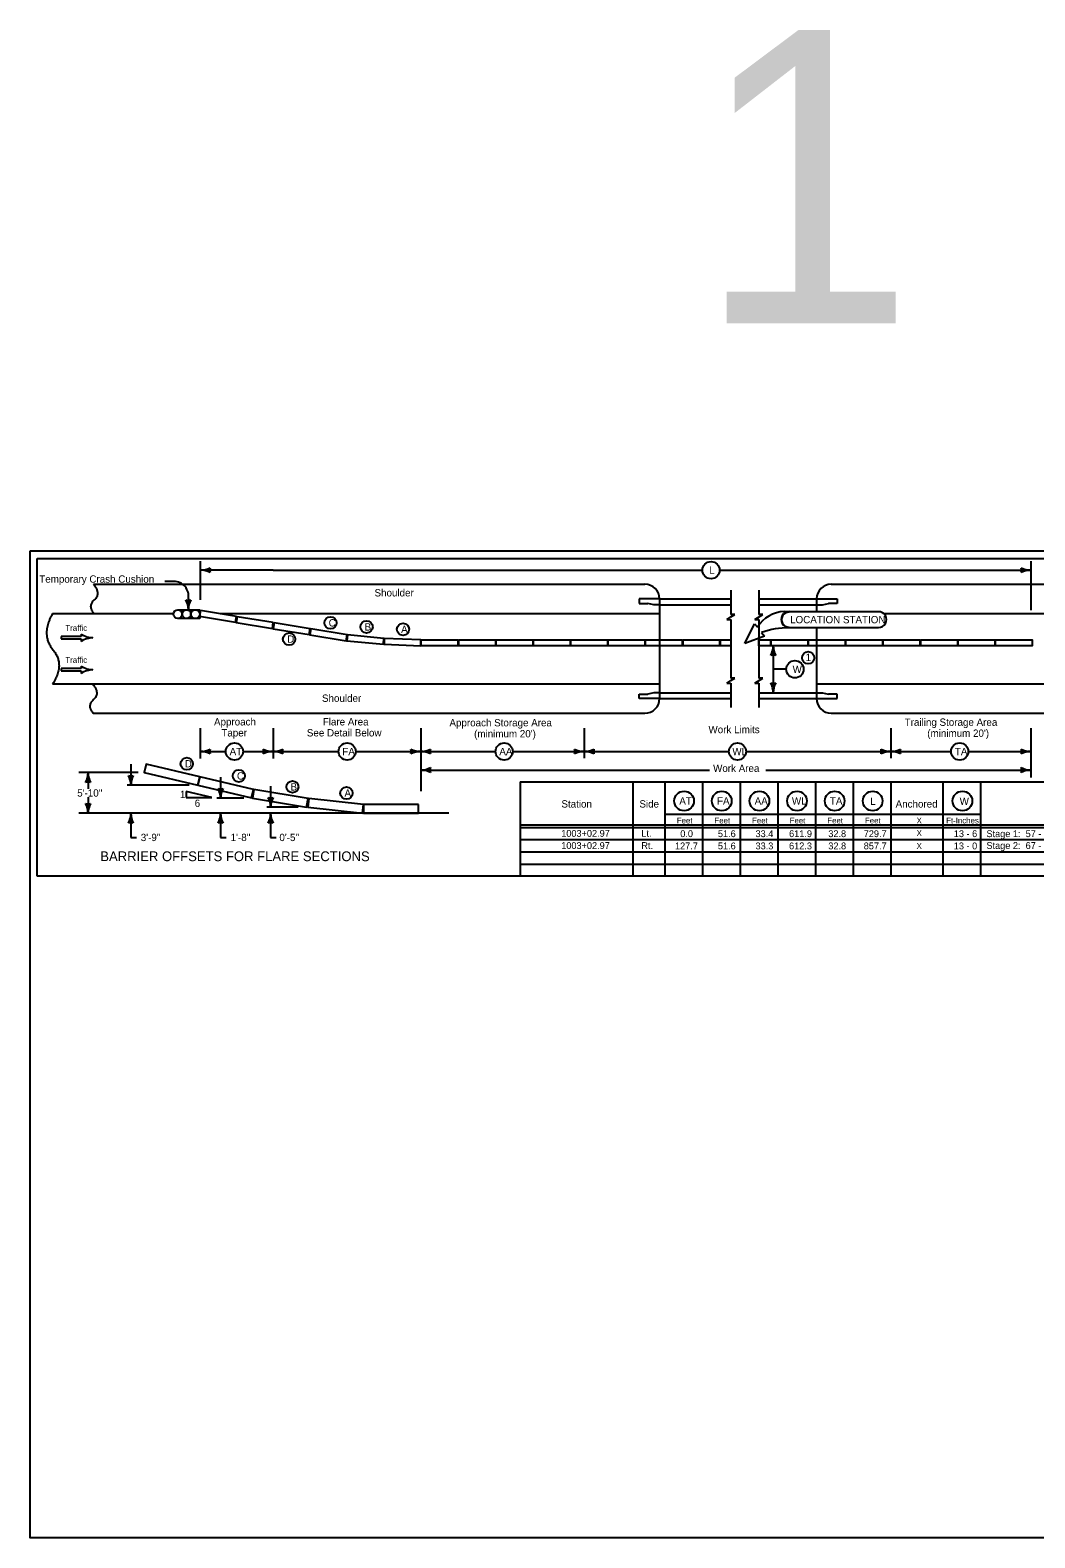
# Model space of a CAD drawing. Extents: x 5601 to 45668, y 7924 to 13839.
# Drawn here: x 10133 to 12188, y 7924 to 11009 of the extents above; entities that cross this region are included whole.
import ezdxf

# ---------------------------------------------------------------- set-up
doc = ezdxf.new("R2010")
doc.units = 0
for name, color, linetype in [('DisCLMLORPoints', 7, 'Continuous'), ('dsnAlignment', 7, 'Continuous'), ('dsnAlignmentCurveData', 7, 'Continuous'), ('dsnAlignmentStation', 7, 'Continuous'), ('Level 1', 7, 'Continuous'), ('Level 12', 7, 'Continuous'), ('Level 63', 7, 'Continuous'), ('Shape', 7, 'Continuous'), ('SheetBorder', 7, 'Continuous'), ('SheetText', 7, 'Continuous')]:
    doc.layers.add(name, color=color, linetype=linetype)

msp = doc.modelspace()

# ---------------------------------------------------------------- linework, layer by layer
at = {"layer": 'DisCLMLORPoints'}
for p, q in [((11135.2, 9352.9), (12386.4, 9352.9)), ((11135.2, 9327.9), (12386.4, 9327.9)), ((11135.2, 9302.9), (12386.4, 9302.9))]:
    msp.add_line(p, q, dxfattribs=at)
at = {"layer": 'dsnAlignment'}
for p, q in [((10146.6, 9927.9), (13251.6, 9927.9)), ((10146.6, 9277.9), (10146.6, 9927.9))]:
    msp.add_line(p, q, dxfattribs=at)
at = {"layer": 'dsnAlignmentStation'}
msp.add_line((13251.6, 9277.9), (10146.6, 9277.9), dxfattribs=at)
at = {"layer": 'Level 1'}
for p, q in [((10480.7, 9922.9), (10480.7, 9843.6)), ((10629.5, 9904.2), (10480.7, 9904.2)), ((10629.5, 9904.2), (11508.1, 9904.2)), ((11543.4, 9904.2), (12180.1, 9904.2)), ((12180.1, 9922.9), (12180.1, 9822.1)), ((10261.9, 9875.3), (11390.4, 9875.3)), ((10426.7, 9881.2), (10408, 9881.2)), ((11771.8, 9875.3), (13120.2, 9875.3)), ((10456.2, 9845.8), (10456.2, 9823.3)), ((11420.4, 9845.3), (11378.4, 9845.3)), ((11378.4, 9845.3), (11378.4, 9836.3)), ((11420.4, 9845.3), (11420.4, 9641.3)), ((11420.4, 9845.3), (11566.4, 9845.3)), ((11566.4, 9863.3), (11566.4, 9813.4)), ((11623.5, 9863.3), (11623.5, 9813.4)), ((11623.5, 9845.3), (11741.8, 9845.3)), ((11741.8, 9845.3), (11783.8, 9845.3)), ((11741.8, 9845.3), (11741.8, 9819.3)), ((11783.8, 9845.3), (11783.8, 9836.3)), ((10178.3, 9815.3), (10424, 9815.3)), ((10434.6, 9823.3), (10479.6, 9823.3)), ((10478.4, 9811), (10479.7, 9810.7)), ((10479.6, 9823.3), (10479.6, 9805.3)), ((10521.4, 9815.3), (11420.4, 9815.3)), ((11378.4, 9836.3), (11396.4, 9836.3)), ((11408.4, 9833.3), (11396.4, 9836.3)), ((11420.4, 9833.3), (11408.4, 9833.3)), ((11420.4, 9833.3), (11566.4, 9833.3)), ((11566.4, 9808.4), (11574.4, 9813.4)), ((11574.4, 9813.4), (11566.4, 9813.4)), ((11615.5, 9803.3), (11631.5, 9813.4)), ((11623.5, 9833.3), (11741.8, 9833.3)), ((11631.5, 9813.4), (11623.5, 9813.4)), ((11675.9, 9819.8), (11685.4, 9820.2)), ((11685.4, 9820.2), (11685.4, 9818.4)), ((11685.4, 9819.3), (11868.5, 9819.3)), ((11741.8, 9833.3), (11753.8, 9833.3)), ((11753.8, 9833.3), (11765.8, 9836.3)), ((11783.8, 9836.3), (11765.8, 9836.3)), ((11879.3, 9815.3), (13210.6, 9815.3)), ((10479.6, 9805.3), (10434.6, 9805.3)), ((10480.2, 9807.3), (10480.2, 9807.3)), ((11558.4, 9803.3), (11566.4, 9808.4)), ((11558.4, 9803.3), (11566.4, 9803.3)), ((11566.4, 9803.3), (11566.4, 9743.3)), ((11594.9, 9754.3), (11615, 9794.3)), ((11615, 9794.3), (11620.7, 9787.3)), ((11615.5, 9803.3), (11623.5, 9803.3)), ((11623.5, 9803.3), (11623.5, 9743.3)), ((11685.4, 9787.7), (11685.4, 9785.9)), ((11685.4, 9786.8), (11868.5, 9786.8)), ((11741.8, 9786.8), (11741.8, 9641.3)), ((10237.1, 9768.1), (10195.9, 9768.1)), ((10195.9, 9768.1), (10195.9, 9763.6)), ((10195.9, 9763.6), (10237.1, 9763.6)), ((10237.1, 9773.4), (10237.1, 9768.1)), ((10237.1, 9763.6), (10237.1, 9758.4)), ((10261.1, 9765.9), (10261.1, 9765.9)), ((11635.1, 9769.3), (11594.9, 9754.3)), ((11629.2, 9776.6), (11635.1, 9769.3)), ((11653.1, 9749.6), (11653.1, 9653.3)), ((11566.4, 9743.3), (11566.4, 9683.2)), ((11623.5, 9743.3), (11623.5, 9683.2)), ((10237.1, 9702.7), (10195.9, 9702.7)), ((10195.9, 9702.7), (10195.9, 9698.2)), ((10195.9, 9698.2), (10237.1, 9698.2)), ((10237.1, 9707.9), (10237.1, 9702.7)), ((10237.1, 9698.2), (10237.1, 9692.9)), ((10261.1, 9700.4), (10261.1, 9700.4)), ((11679.7, 9701.4), (11653.1, 9701.4)), ((10178.3, 9671.3), (11420.4, 9671.3)), ((11558.4, 9673.1), (11566.4, 9678.2)), ((11558.4, 9673.1), (11566.4, 9673.1)), ((11566.4, 9678.2), (11574.4, 9683.2)), ((11574.4, 9683.2), (11566.4, 9683.2)), ((11566.4, 9673.1), (11566.4, 9623.3)), ((11615.5, 9673.1), (11631.5, 9683.2)), ((11615.5, 9673.1), (11623.5, 9673.1)), ((11631.5, 9683.2), (11623.5, 9683.2)), ((11623.5, 9673.1), (11623.5, 9623.3)), ((11741.8, 9671.3), (13210.6, 9671.3)), ((11378.4, 9650.3), (11396.4, 9650.3)), ((11378.4, 9641.3), (11378.4, 9650.3)), ((11420.4, 9641.3), (11378.4, 9641.3)), ((11408.4, 9653.3), (11396.4, 9650.3)), ((11420.4, 9653.3), (11408.4, 9653.3)), ((11420.4, 9653.3), (11566.4, 9653.3)), ((11420.4, 9641.3), (11566.4, 9641.3)), ((11623.5, 9653.3), (11741.8, 9653.3)), ((11623.5, 9641.3), (11741.8, 9641.3)), ((11741.8, 9653.3), (11753.8, 9653.3)), ((11741.8, 9641.3), (11783.8, 9641.3)), ((11753.8, 9653.3), (11765.8, 9650.3)), ((11783.8, 9650.3), (11765.8, 9650.3)), ((11783.8, 9641.3), (11783.8, 9650.3)), ((10261.9, 9611.3), (11390.4, 9611.3)), ((11771.8, 9611.3), (13120.2, 9611.3)), ((10480.7, 9580.7), (10480.7, 9518.5)), ((10629.5, 9580.9), (10629.5, 9518.5)), ((10931.7, 9580.9), (10931.7, 9451.8)), ((11266.2, 9580.9), (11266.2, 9519.7)), ((11893.6, 9580.9), (11893.6, 9519.7)), ((12180.1, 9580.9), (12180.1, 9480.1)), ((10338.6, 9507.3), (10338.6, 9463.9)), ((10480.7, 9533.1), (10532.8, 9533.1)), ((10568.2, 9533.1), (10629.5, 9533.1)), ((10629.5, 9533.1), (10763, 9533.1)), ((10798.3, 9533.1), (10931.7, 9533.1)), ((10931.7, 9533.1), (11084.7, 9533.1)), ((11120, 9533.1), (11419.2, 9533.1)), ((11419.2, 9533.1), (11562.4, 9533.1)), ((11597.4, 9533.1), (11740.6, 9533.1)), ((11610.1, 9533.1), (11740.6, 9533.1)), ((11740.6, 9533.1), (12016.9, 9533.1)), ((12052.2, 9533.1), (12180.1, 9533.1)), ((10353.2, 9489.8), (10232, 9489.8)), ((10251, 9489.8), (10251, 9456.4)), ((10522.2, 9480.9), (10522.2, 9437.5)), ((10931.7, 9495.2), (11522.5, 9495.2)), ((11637.8, 9495.2), (12180.1, 9495.2)), ((11639.2, 9495.2), (11740.6, 9495.2)), ((10458.1, 9463.9), (10330.9, 9463.9)), ((10624.6, 9462.4), (10624.6, 9418.9)), ((11366.2, 9277.9), (11366.2, 9470.9)), ((11432.2, 9277.9), (11432.2, 9470.9)), ((11432.2, 9277.9), (11432.2, 9470.9)), ((11509.2, 9277.9), (11509.2, 9470.9)), ((11586.2, 9277.9), (11586.2, 9470.9)), ((11586.2, 9277.9), (11586.2, 9470.9)), ((11663.2, 9277.9), (11663.2, 9470.9)), ((11740.2, 9277.9), (11740.2, 9470.9)), ((11817.2, 9277.9), (11817.2, 9470.9)), ((10251, 9440), (10251, 9406.6)), ((10570, 9437.5), (10514.4, 9437.5)), ((10680.9, 9418.9), (10616.8, 9418.9)), ((10989.4, 9406.6), (10232, 9406.6)), ((10338.6, 9406.6), (10338.6, 9357.3)), ((10522.2, 9406.6), (10522.2, 9357.3)), ((10624.6, 9406.6), (10624.6, 9379.6)), ((10624.6, 9379.6), (10624.6, 9357.3)), ((11135.2, 9382.9), (12386.4, 9382.9)), ((11432.2, 9405.1), (12077.8, 9405.1)), ((10338.6, 9357.3), (10349.8, 9357.3)), ((10522.2, 9357.3), (10533.3, 9357.3)), ((10624.6, 9357.3), (10635.7, 9357.3)), ((11135.2, 9377.9), (12386.4, 9377.9))]:
    msp.add_line(p, q, dxfattribs=at)
for points in [[(10554.8, 9809.4), (10480.8, 9821.6), (10478.9, 9809.7), (10552.9, 9797.6)], [(10630.1, 9796.9), (10556.1, 9809), (10554.2, 9797.2), (10628.2, 9785)], [(10705.5, 9784.1), (10631.5, 9796.2), (10629.5, 9784.4), (10703.6, 9772.3)], [(10781, 9771.7), (10707, 9783.9), (10705, 9772), (10779, 9759.9)], [(10856.4, 9764.5), (10781.7, 9771.6), (10780.6, 9759.7), (10855.3, 9752.6)], [(10932.2, 9761.6), (10857.2, 9764.6), (10856.8, 9752.6), (10931.7, 9749.6)], [(10932.9, 9761.6), (11007.9, 9761.6), (11007.9, 9749.6), (10932.9, 9749.6)], [(11009.4, 9761.6), (11084.4, 9761.6), (11084.4, 9749.6), (11009.4, 9749.6)], [(11085.9, 9761.6), (11160.9, 9761.6), (11160.9, 9749.6), (11085.9, 9749.6)], [(11162.4, 9761.6), (11237.4, 9761.6), (11237.4, 9749.6), (11162.4, 9749.6)], [(11238.9, 9761.6), (11313.9, 9761.6), (11313.9, 9749.6), (11238.9, 9749.6)], [(11315.4, 9761.6), (11390.4, 9761.6), (11390.4, 9749.6), (11315.4, 9749.6)], [(11391.9, 9761.6), (11466.9, 9761.6), (11466.9, 9749.6), (11391.9, 9749.6)], [(11468.4, 9761.6), (11543.4, 9761.6), (11543.4, 9749.6), (11468.4, 9749.6)], [(11648.8, 9761.6), (11723.8, 9761.6), (11723.8, 9749.6), (11648.8, 9749.6)], [(11725.3, 9761.6), (11800.3, 9761.6), (11800.3, 9749.6), (11725.3, 9749.6)], [(11801.8, 9761.6), (11876.8, 9761.6), (11876.8, 9749.6), (11801.8, 9749.6)], [(11878.3, 9761.6), (11953.3, 9761.6), (11953.3, 9749.6), (11878.3, 9749.6)], [(11954.8, 9761.6), (12029.8, 9761.6), (12029.8, 9749.6), (11954.8, 9749.6)], [(12031.3, 9761.6), (12106.3, 9761.6), (12106.3, 9749.6), (12031.3, 9749.6)], [(12107.8, 9761.6), (12182.8, 9761.6), (12182.8, 9749.6), (12107.8, 9749.6)], [(10479.4, 9481.5), (10369.9, 9507.4), (10365.8, 9489.8), (10475.3, 9463.9)], [(10589.2, 9455.5), (10479.7, 9481.4), (10475.6, 9463.9), (10585.1, 9438)], [(10701.3, 9436.8), (10590.3, 9455.2), (10587.4, 9437.5), (10698.3, 9419)], [(10814.4, 9424.5), (10702.5, 9436.8), (10700.6, 9418.9), (10812.4, 9406.6)], [(10926.9, 9424.6), (10814.4, 9424.6), (10814.4, 9406.6), (10926.9, 9406.6)]]:
    msp.add_lwpolyline(points, close=True, dxfattribs=at)
for points in [[(11566.4, 9749.6), (11544.9, 9749.6), (11544.9, 9761.6), (11566.4, 9761.6)], [(11566.4, 9761.6), (11566.4, 9749.6)], [(11623.5, 9749.6), (11623.5, 9761.6)], [(11623.5, 9761.6), (11647.3, 9761.6), (11647.3, 9749.6), (11623.5, 9749.6)]]:
    msp.add_lwpolyline(points, dxfattribs=at)
for centre, radius in [((11525.7, 9904.2), 17.6), ((10434.6, 9814.3), 9), ((10452.6, 9814.3), 9), ((10470.6, 9814.3), 9), ((10747.2, 9796.4), 12.5), ((10821, 9788), 12.5), ((10895.5, 9783.1), 12.5), ((10662.3, 9763.2), 12.5), ((11697.4, 9701.4), 17.6), ((11724.5, 9724.9), 12.5), ((10550.5, 9533.1), 17.6), ((10781.1, 9533.1), 17.6), ((11102.3, 9533.1), 17.6), ((11579.9, 9533.1), 17.6), ((12034.5, 9533.1), 17.6), ((10452.9, 9508), 12.5), ((10559.6, 9483.1), 12.5), ((10669.3, 9460.8), 12.2), ((10779.6, 9448.1), 12.5), ((11470.7, 9431.9), 20.1), ((11547.7, 9431.9), 20.1), ((11624.7, 9431.9), 20.1), ((11701.7, 9431.9), 20.1), ((11778.7, 9431.9), 20.1), ((11856.5, 9431.9), 20.1), ((12040.1, 9431.9), 20.1)]:
    msp.add_circle(centre, radius, dxfattribs=at)
for centre, radius, start, end in [((10480.7, 9946.7), 42.5, 270, 298.0725), ((10480.7, 9861.7), 42.5, 61.9275, 90), ((10516.3, 9904.2), 16.4, 162.2666, 197.7334), ((12144.5, 9904.2), 16.4, 342.2666, 17.7333), ((12180.1, 9946.7), 42.5, 241.9275, 270), ((12180.1, 9861.7), 42.5, 90, 118.0725), ((10426.7, 9851.2), 30, 349.6463, 90), ((11390.4, 9845.3), 30, 0, 90), ((11771.8, 9845.3), 30, 90, 180), ((10456.2, 9858.9), 16.4, 252.2666, 287.7333), ((10413.7, 9823.3), 42.5, 360, 28.0725), ((10498.7, 9823.3), 42.5, 151.9275, 180), ((10263, 9814.2), 48.4, 237.618, 267.648), ((10263, 9717.6), 48.4, 92.352, 122.382), ((11610.6, 9749.6), 42.5, 331.9275, 0), ((11695.6, 9749.6), 42.5, 180, 208.0725), ((11653.1, 9713.9), 16.4, 72.2666, 107.7334), ((10263, 9748.7), 48.4, 237.618, 267.648), ((10263, 9652.1), 48.4, 92.352, 122.382), ((11653.1, 9688.9), 16.4, 252.2666, 287.7334), ((11610.6, 9653.3), 42.5, 0, 28.0725), ((11695.6, 9653.3), 42.5, 151.9275, 180), ((11390.4, 9641.3), 30, 270, 360), ((11771.8, 9641.3), 30, 180, 270), ((10480.7, 9575.6), 42.5, 270, 298.0725), ((10516.3, 9533.1), 16.4, 162.2666, 197.7334), ((10593.9, 9533.1), 16.4, 342.2666, 17.7333), ((10629.5, 9575.6), 42.5, 241.9275, 270), ((10629.5, 9575.6), 42.5, 270, 298.0725), ((10665.2, 9533.1), 16.4, 162.2666, 197.7334), ((10896.1, 9533.1), 16.4, 342.2666, 17.7333), ((10931.7, 9575.6), 42.5, 241.9275, 270), ((10931.7, 9575.6), 42.5, 270, 298.0725), ((10967.3, 9533.1), 16.4, 162.2666, 197.7334), ((11230.6, 9533.1), 16.4, 342.2666, 17.7333), ((11266.2, 9575.6), 42.5, 241.9275, 270), ((11266.2, 9575.6), 42.5, 270, 298.0725), ((11301.8, 9533.1), 16.4, 162.2666, 197.7334), ((11858, 9533.1), 16.4, 342.2666, 17.7333), ((11893.6, 9575.6), 42.5, 241.9275, 270), ((11893.6, 9575.6), 42.5, 270, 298.0725), ((11929.2, 9533.1), 16.4, 162.2666, 197.7334), ((12144.5, 9533.1), 16.4, 342.2666, 17.7333), ((12180.1, 9575.6), 42.5, 241.9275, 270), ((10480.7, 9490.6), 42.5, 61.9275, 90), ((10629.5, 9490.6), 42.5, 90, 118.0725), ((10629.5, 9490.6), 42.5, 61.9275, 90), ((10931.7, 9490.6), 42.5, 90, 118.0725), ((10931.7, 9490.6), 42.5, 61.9275, 90), ((11266.2, 9490.6), 42.5, 90, 118.0725), ((11266.2, 9490.6), 42.5, 61.9275, 90), ((11893.6, 9490.6), 42.5, 90, 118.0725), ((11893.6, 9490.6), 42.5, 61.9275, 90), ((12180.1, 9490.6), 42.5, 90, 118.0725), ((10208.5, 9489.8), 42.5, 331.9275, 0), ((10293.5, 9489.8), 42.5, 180, 208.0725), ((10338.6, 9499.5), 16.4, 252.2666, 287.7334), ((10296.1, 9463.9), 42.5, 0, 28.0725), ((10381.1, 9463.9), 42.5, 151.9275, 180), ((10931.7, 9537.7), 42.5, 270, 298.0725), ((10931.7, 9452.7), 42.5, 61.9275, 90), ((10967.3, 9495.2), 16.4, 162.2666, 197.7334), ((12144.5, 9495.2), 16.4, 342.2666, 17.7333), ((12180.1, 9537.7), 42.5, 241.9275, 270), ((12180.1, 9452.7), 42.5, 90, 118.0725), ((10251, 9454.2), 16.4, 72.2666, 107.7334), ((10522.2, 9473.1), 16.4, 252.2666, 287.7334), ((10479.7, 9437.5), 42.5, 0, 28.0725), ((10564.7, 9437.5), 42.5, 151.9275, 180), ((10251, 9442.2), 16.4, 252.2666, 287.7334), ((10208.5, 9406.6), 42.5, 0, 28.0725), ((10293.5, 9406.6), 42.5, 151.9275, 180), ((10624.6, 9454.5), 16.4, 252.2666, 287.7334), ((10582.1, 9418.9), 42.5, 0, 28.0725), ((10667.1, 9418.9), 42.5, 151.9275, 180), ((10296.1, 9406.6), 42.5, 331.9275, 0), ((10338.6, 9370.9), 16.4, 72.2666, 107.7334), ((10381.1, 9406.6), 42.5, 180, 208.0725), ((10479.7, 9406.6), 42.5, 331.9275, 0), ((10522.2, 9370.9), 16.4, 72.2666, 107.7334), ((10564.7, 9406.6), 42.5, 180, 208.0725), ((10582.1, 9406.6), 42.5, 331.9275, 0), ((10624.6, 9370.9), 16.4, 72.2666, 107.7334), ((10667.1, 9406.6), 42.5, 180, 208.0725)]:
    msp.add_arc(centre, radius, start, end, dxfattribs=at)
for centre, major_axis, start_param, end_param in [((11680.4, 9749.6), (-70.8, 0), 4.776871, 5.71778), ((11685.4, 9803), (-16.3, 0), 4.712389, 7.853982), ((11685.4, 9803), (15.4, 0), 1.570796, 4.712389), ((11868.5, 9803), (16.3, 0), 4.712389, 7.853982), ((11682.5, 9629.8), (-156.9, 0), 4.694293, 5.059134)]:
    msp.add_ellipse(centre, major_axis=major_axis, ratio=0.995025, start_param=start_param, end_param=end_param, dxfattribs=at)
for points in [[(10261.9, 9875.3), (10278, 9856), (10249.1, 9830.4), (10263.5, 9815.3)], [(10178.3, 9815.3), (10153.7, 9772.6), (10204.4, 9710.5), (10178.3, 9671.3)], [(10260.3, 9671.3), (10276.4, 9651.9), (10247.4, 9626.3), (10261.9, 9611.3)]]:
    msp.add_open_spline(points, degree=2, dxfattribs=at)
at = {"layer": 'Level 12'}
for p, q in [((10504.2, 9438.9), (10451.6, 9451.3)), ((10451.6, 9451.3), (10451.6, 9438.9)), ((10451.6, 9438.9), (10504.2, 9438.9))]:
    msp.add_line(p, q, dxfattribs=at)
at = {"layer": 'Level 63'}
for p, q in [((11135.2, 9470.9), (11135.2, 9277.9)), ((11135.2, 9470.9), (12386.4, 9470.9)), ((11894.2, 9277.9), (11894.2, 9470.9)), ((12000.8, 9277.9), (12000.8, 9470.9)), ((12077.8, 9277.9), (12077.8, 9470.9))]:
    msp.add_line(p, q, dxfattribs=at)
at = {"layer": 'SheetBorder'}
msp.add_lwpolyline([(10132.5, 9944), (13267.5, 9944), (13267.5, 7924), (10132.5, 7924)], close=True, dxfattribs=at)

# ---------------------------------------------------------------- texts
at = {"layer": 'dsnAlignmentCurveData'}
for s, p in [('1003+02.97', (11219.2, 9358.6)), ('Lt.', (11383.2, 9358.6)), ('0.0', (11462.8, 9357.9)), ('51.6', (11539.8, 9357.9)), ('33.4', (11616.8, 9357.9)), ('611.9', (11685.5, 9357.9)), ('32.8', (11765.7, 9357.9)), ('729.7', (11838.2, 9357.9)), ('13 - 6', (12022.5, 9357.9)), ("Stage 1:  57 - 12.5' TBR Sections", (12089.3, 9357.9)), ("Stage 2:  67 - 12.5' TBR Sections", (12089.3, 9333.7)), ('1003+02.97', (11219.2, 9333.6)), ('Rt.', (11383.2, 9333.6)), ('127.7', (11452, 9332.9)), ('51.6', (11539.8, 9332.9)), ('33.3', (11616.8, 9332.9)), ('612.3', (11685.4, 9332.9)), ('32.8', (11765.7, 9332.9)), ('857.7', (11838.2, 9332.9)), ('13 - 0', (12022.5, 9332.9))]:
    msp.add_text(s, height=14, dxfattribs=at).set_placement(p)
at = {"layer": 'Level 12'}
for s, height, p in [('L', 15, (11521.8, 9896.7)), ('Temporary Crash Cushion', 15, (10151.2, 9878.5)), ('Shoulder', 15, (10837.2, 9850.4)), ('Traffic', 12, (10204.6, 9779.9)), ('C', 15, (10743.3, 9788.9)), ('B', 15, (10817, 9780.5)), ('A', 15, (10891.6, 9775.6)), ('LOCATION STATION', 15, (11687.6, 9795.5)), ('D', 15, (10658.4, 9755.7)), ('Traffic', 12, (10204.6, 9714.4)), ('1', 15, (11719.2, 9718.3)), ('W', 15, (11692.7, 9693.9)), ('Shoulder', 15, (10729.7, 9634.7)), ('Approach', 15, (10508.7, 9586.4)), ('Flare Area', 15, (10731.3, 9586.4)), ('Approach Storage Area', 15, (10990.5, 9584.5)), ('Trailing Storage Area', 15, (11922, 9585.6)), ('Taper', 15, (10523.8, 9563.9)), ('See Detail Below', 15, (10698.7, 9563.9)), ("(minimum 20')", 15, (11040.9, 9562)), ('Work Limits', 15, (11520.5, 9570.6)), ("(minimum 20')", 15, (11968.2, 9563.1)), ('AT', 15, (10540.7, 9525.6)), ('FA', 15, (10771.3, 9525.6)), ('AA', 15, (11092.6, 9525.6)), ('WL', 15, (11569.4, 9525.6)), ('TA', 15, (12024.7, 9525.6)), ('D', 15, (10449, 9500.5)), ('Work Area', 15, (11530, 9491.3)), ('C', 15, (10555.7, 9475.6)), ("5'-10''", 15, (10228.8, 9440.8)), ('1', 15, (10439, 9437.7)), ('B', 15, (10665.3, 9453.3)), ('A', 15, (10775.7, 9440.6)), ('6', 15, (10469.2, 9419.7)), ('Station', 15, (11219.6, 9418.4)), ('Side', 15, (11379.2, 9418.4)), ('AT', 15, (11460.9, 9424.4)), ('FA', 15, (11538, 9424.4)), ('AA', 15, (11615, 9424.4)), ('WL', 15, (11691.2, 9424.4)), ('TA', 15, (11768.9, 9424.4)), ('L', 15, (11851.6, 9423.9)), ('Anchored', 15, (11903.5, 9418.4)), ('W', 15, (12034.5, 9423.9)), ('Feet', 12, (11455.7, 9385.9)), ('Feet', 12, (11532.7, 9385.9)), ('Feet', 12, (11609.7, 9385.9)), ('Feet', 12, (11686.7, 9385.9)), ('Feet', 12, (11763.7, 9385.9)), ('Feet', 12, (11840.7, 9385.9)), ('X', 12, (11946.4, 9385.9)), ('Ft-Inches', 12, (12006.9, 9385.9)), ("3'-9''", 15, (10358.9, 9349.8)), ("1'-8''", 15, (10542.8, 9349.8)), ("0'-5''", 15, (10642.5, 9349.8)), ('X', 12, (11946.4, 9360.2)), ('X', 12, (11946.4, 9333.8))]:
    msp.add_text(s, height=height, dxfattribs=at).set_placement(p)
at = {"layer": 'Shape'}
msp.add_text('BARRIER OFFSETS FOR FLARE SECTIONS', height=20, dxfattribs=at).set_placement((10276, 9308.7))
at = {"layer": 'SheetText'}
msp.add_text('1', height=600, dxfattribs=at).set_placement((11496.6, 10409.2))

doc.saveas('drawing.dxf')
